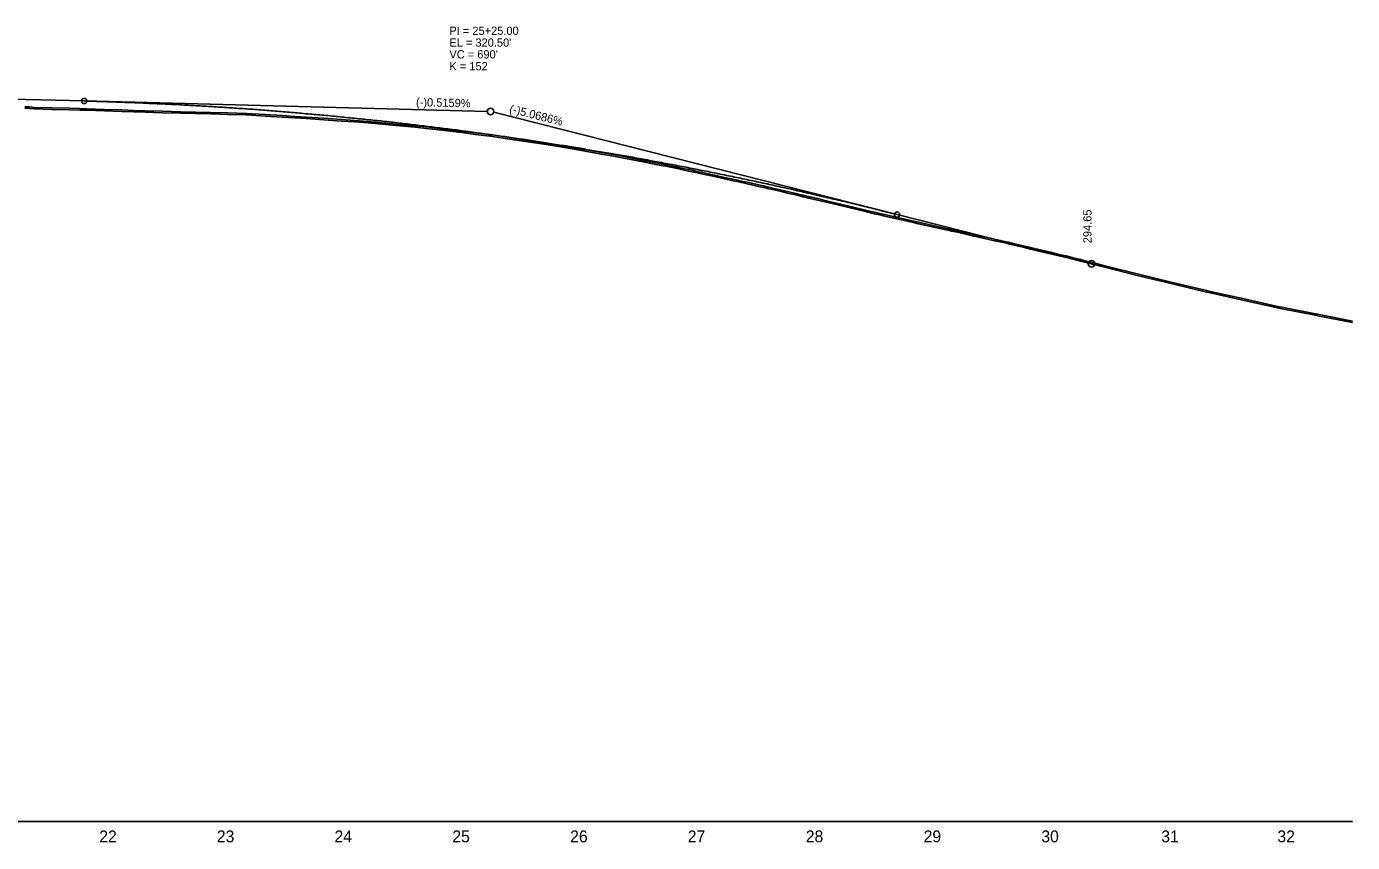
# Model space of a CAD drawing. Extents: x 2111382 to 2119088, y 667477 to 672158.
# Drawn here: x 2113830 to 2114956, y 667477 to 668169 of the extents above; entities that cross this region are included whole.
import ezdxf

# ---------------------------------------------------------------- set-up
doc = ezdxf.new("R2010")
doc.units = 0
for name, color, linetype in [('Exist Profile Cell', 7, 'Continuous'), ('Exist Vertical Profile Ground Line', 7, 'Continuous'), ('Exist Vertical Profile Horizontal Axis Label Major', 7, 'Continuous'), ('Prop Vertical Profile Curve Label', 7, 'Continuous'), ('Prop Vertical Profile Grade', 7, 'Continuous'), ('Prop Vertical Profile Grade Label', 7, 'Continuous'), ('Prop VPI Label', 7, 'Continuous'), ('Scratch_Level_2', 7, 'Continuous')]:
    doc.layers.add(name, color=color, linetype=linetype)

msp = doc.modelspace()

# ---------------------------------------------------------------- linework, layer by layer
at = {"layer": 'Exist Profile Cell'}
msp.add_line((2112699, 667494.5), (2114955.5, 667494.5), dxfattribs=at)
at = {"layer": 'Exist Vertical Profile Ground Line'}
for points in [[(2113828.6, 668099.7), (2113830.4, 668099.7), (2113832.7, 668099.6), (2113836.7, 668099.3), (2113851.5, 668098.8), (2113866.7, 668098.4), (2113875.2, 668098.2), (2113880.9, 668098), (2113896.2, 668097.5), (2113910.9, 668097), (2113921.2, 668096.7), (2113930.8, 668096.3), (2113945.6, 668096), (2113960.8, 668095.6), (2113973.4, 668095.3), (2113986.2, 668095), (2114001, 668094.5), (2114016.3, 668094.2), (2114017.1, 668094.1), (2114032.5, 668093.1), (2114047.1, 668092.3), (2114057.8, 668091.6), (2114067.5, 668091.1), (2114082.3, 668090), (2114097.5, 668088.9), (2114108.4, 668088.2), (2114120, 668087.3), (2114134.8, 668085.9), (2114150, 668084.5), (2114159.9, 668083.6), (2114169.6, 668082.7), (2114184.8, 668080.9), (2114199.6, 668079.1), (2114211.3, 668077.6), (2114223.7, 668076.1), (2114238.4, 668073.9), (2114253.7, 668071.6), (2114267.5, 668069.5), (2114281.9, 668067.3), (2114296.5, 668064.7), (2114311.9, 668062), (2114317.9, 668060.9), (2114325.1, 668059.7), (2114338.5, 668057.2), (2114355, 668054), (2114361.3, 668052.7), (2114368.8, 668051.3), (2114373.8, 668050.3), (2114379.9, 668049.1), (2114381.3, 668048.8), (2114386, 668047.8), (2114392, 668046.5), (2114395.2, 668045.8), (2114398.1, 668045.2), (2114404.2, 668043.9), (2114409.7, 668042.7), (2114410.2, 668042.6), (2114416.3, 668041.2), (2114422.5, 668039.8)], [(2114422.5, 668039.8), (2114428.4, 668038.5), (2114434.5, 668037.2), (2114439.6, 668036.1), (2114440.6, 668035.9), (2114446.6, 668034.6), (2114452.7, 668033.2), (2114455.5, 668032.6), (2114457.3, 668032.1), (2114458.8, 668031.8), (2114464.8, 668030.4), (2114470.9, 668029), (2114476, 668027.8), (2114477, 668027.5), (2114483.1, 668026.2), (2114487.3, 668025.2), (2114489.1, 668024.7), (2114489.9, 668024.6), (2114495.2, 668023.3), (2114501.3, 668021.8), (2114510.3, 668019.7), (2114519.8, 668017.4), (2114542.1, 668012.1), (2114549.8, 668010.3), (2114555.4, 668009), (2114557.3, 668008.6), (2114581.8, 668003.1), (2114587.2, 668001.8), (2114609.3, 667996.9), (2114613.5, 667995.9), (2114615.3, 667995.5), (2114617.1, 667995.1), (2114621.4, 667994.2), (2114627.5, 667992.8), (2114632.9, 667991.6), (2114633.5, 667991.4), (2114634.4, 667991.2), (2114639.6, 667990.1), (2114645.7, 667988.7), (2114651.7, 667987.4), (2114657.8, 667986), (2114662.9, 667984.9), (2114663.9, 667984.6), (2114664.4, 667984.5), (2114669.9, 667983.2), (2114676, 667981.8), (2114682.1, 667980.3), (2114684.6, 667979.7), (2114685.2, 667979.6), (2114686.1, 667979.4), (2114688.1, 667978.9), (2114694.2, 667977.5), (2114700.3, 667976), (2114706.3, 667974.6), (2114712.4, 667973.1), (2114715.2, 667972.5), (2114715.6, 667972.4), (2114718.5, 667971.6), (2114724.6, 667970.1), (2114730.6, 667968.6), (2114736.7, 667967), (2114745.2, 667964.9), (2114775.1, 667957.3), (2114801.5, 667951), (2114831.5, 667943.8), (2114833.5, 667943.3), (2114863.5, 667936.7), (2114893.4, 667930.1), (2114895.6, 667929.7), (2114925.5, 667923.8), (2114925.9, 667923.7), (2114955.5, 667917.9)]]:
    msp.add_lwpolyline(points, dxfattribs=at)
at = {"layer": 'Prop Vertical Profile Curve Label'}
for centre in [(2113879, 668105.9), (2114569, 668009.5)]:
    msp.add_circle(centre, 2.25, dxfattribs=at)
at = {"layer": 'Prop Vertical Profile Grade'}
for p, q in [((2113559, 668114.1), (2113879, 668105.9)), ((2114569, 668009.5), (2114734, 667967.7))]:
    msp.add_line(p, q, dxfattribs=at)
msp.add_spline([(2113879, 668105.9), (2113892.8, 668105.5), (2113906.6, 668105), (2113920.4, 668104.5), (2113934.2, 668103.9), (2113948, 668103.3), (2113961.8, 668102.6), (2113975.6, 668101.8), (2113989.4, 668101), (2114003.2, 668100.1), (2114017, 668099.2), (2114030.8, 668098.2), (2114044.6, 668097.1), (2114058.4, 668095.9), (2114072.2, 668094.7), (2114086, 668093.5), (2114099.8, 668092.1), (2114113.6, 668090.7), (2114127.4, 668089.3), (2114141.2, 668087.8), (2114155, 668086.2), (2114168.8, 668084.5), (2114182.6, 668082.8), (2114196.4, 668081.1), (2114210.2, 668079.2), (2114224, 668077.3), (2114237.8, 668075.4), (2114251.6, 668073.4), (2114265.4, 668071.3), (2114279.2, 668069.1), (2114293, 668066.9), (2114306.8, 668064.6), (2114320.6, 668062.3), (2114334.4, 668059.9), (2114348.2, 668057.5), (2114362, 668054.9), (2114375.8, 668052.3), (2114389.6, 668049.7), (2114403.4, 668047), (2114417.2, 668044.2), (2114431, 668041.4), (2114444.8, 668038.5), (2114458.6, 668035.5), (2114472.4, 668032.5), (2114486.2, 668029.4), (2114500, 668026.2), (2114513.8, 668023), (2114527.6, 668019.8), (2114541.4, 668016.4), (2114555.2, 668013), (2114569, 668009.5)], degree=3, dxfattribs=at)
at = {"layer": 'Prop VPI Label'}
for p, q in [((2113879, 668105.9), (2114221.3, 668097)), ((2114569, 668009.5), (2114226.7, 668096.3))]:
    msp.add_line(p, q, dxfattribs=at)
for centre in [(2114224, 668097), (2114734, 667967.7)]:
    msp.add_circle(centre, 2.75, dxfattribs=at)
at = {"layer": 'Scratch_Level_2'}
for points in [[(2113828.6, 668100.9), (2113830.4, 668100.9), (2113832.7, 668100.9), (2113836.7, 668100.5), (2113851.5, 668100.1), (2113866.7, 668099.7), (2113875.2, 668099.4), (2113880.9, 668099.2), (2113896.2, 668098.7), (2113910.9, 668098.3), (2113921.2, 668097.9), (2113930.8, 668097.6), (2113945.6, 668097.2), (2113960.8, 668096.8), (2113973.4, 668096.5), (2113986.2, 668096.2), (2114001, 668095.8), (2114016.3, 668095.4), (2114017.1, 668095.4), (2114032.5, 668094.4), (2114047.1, 668093.6), (2114057.8, 668092.8), (2114067.5, 668092.3), (2114082.3, 668091.2), (2114097.5, 668090.2), (2114108.4, 668089.4), (2114120, 668088.6), (2114134.8, 668087.2), (2114150, 668085.8), (2114159.9, 668084.9), (2114169.6, 668084), (2114184.8, 668082.1), (2114199.6, 668080.3), (2114211.3, 668078.9), (2114223.7, 668077.4), (2114238.4, 668075.2), (2114253.7, 668072.8), (2114267.5, 668070.7), (2114281.9, 668068.5), (2114296.5, 668065.9), (2114311.9, 668063.3), (2114317.9, 668062.2), (2114325.1, 668061), (2114338.5, 668058.4), (2114355, 668055.2), (2114361.3, 668054), (2114368.8, 668052.6), (2114373.8, 668051.5), (2114379.9, 668050.3), (2114381.3, 668050), (2114386, 668049), (2114392, 668047.8), (2114395.2, 668047.1), (2114398.1, 668046.5), (2114404.2, 668045.1), (2114409.7, 668043.9), (2114410.2, 668043.8), (2114416.3, 668042.5), (2114422.5, 668041.1)], [(2114422.5, 668041.1), (2114428.4, 668039.8), (2114434.5, 668038.5), (2114439.6, 668037.4), (2114440.6, 668037.2), (2114446.6, 668035.8), (2114452.7, 668034.5), (2114455.5, 668033.8), (2114457.3, 668033.4), (2114458.8, 668033), (2114464.8, 668031.6), (2114470.9, 668030.2), (2114476, 668029), (2114477, 668028.8), (2114483.1, 668027.4), (2114487.3, 668026.4), (2114489.1, 668026), (2114489.9, 668025.8), (2114495.2, 668024.5), (2114501.3, 668023.1), (2114510.3, 668020.9), (2114519.8, 668018.7), (2114542.1, 668013.3), (2114549.8, 668011.5), (2114555.4, 668010.2), (2114557.3, 668009.8), (2114581.8, 668004.3), (2114587.2, 668003.1), (2114609.3, 667998.1), (2114613.5, 667997.2), (2114615.3, 667996.8), (2114617.1, 667996.4), (2114621.4, 667995.4), (2114627.5, 667994.1), (2114632.9, 667992.8), (2114633.5, 667992.7), (2114634.4, 667992.5), (2114639.6, 667991.3), (2114645.7, 667990), (2114651.7, 667988.6), (2114657.8, 667987.2), (2114662.9, 667986.1), (2114663.9, 667985.9), (2114664.4, 667985.8), (2114669.9, 667984.5), (2114676, 667983), (2114682.1, 667981.6), (2114684.6, 667981), (2114685.2, 667980.8), (2114686.1, 667980.6), (2114688.1, 667980.1), (2114694.2, 667978.7), (2114700.3, 667977.3), (2114706.3, 667975.8), (2114712.4, 667974.4), (2114715.2, 667973.7), (2114715.6, 667973.6), (2114718.5, 667972.9), (2114724.6, 667971.4), (2114730.6, 667969.8), (2114736.7, 667968.3), (2114745.2, 667966.1), (2114775.1, 667958.6), (2114801.5, 667952.2), (2114831.5, 667945), (2114833.5, 667944.6), (2114863.5, 667938), (2114893.4, 667931.4), (2114895.6, 667930.9), (2114925.5, 667925), (2114925.9, 667925), (2114955.5, 667919.1)]]:
    msp.add_lwpolyline(points, dxfattribs=at)

# ---------------------------------------------------------------- texts
at = {"layer": 'Exist Vertical Profile Horizontal Axis Label Major'}
for s, p in [('22', (2113891.8, 667477)), ('23', (2113991.6, 667477)), ('24', (2114091.5, 667477)), ('25', (2114191.5, 667477)), ('26', (2114291.5, 667477)), ('27', (2114391.3, 667477)), ('28', (2114491.5, 667477)), ('29', (2114591.5, 667477)), ('30', (2114691.4, 667477)), ('31', (2114793.2, 667477)), ('32', (2114891.8, 667477))]:
    msp.add_text(s, height=10, dxfattribs=at).set_placement(p)
at = {"layer": 'Prop Vertical Profile Curve Label'}
for s, p in [("VC = 690'", (2114189, 668142)), ('K = 152', (2114189, 668131.9))]:
    msp.add_text(s, height=7, dxfattribs=at).set_placement(p)
at = {"layer": 'Prop Vertical Profile Grade Label'}
for s, rotation, p in [('(-)0.5159%', 358.5225, (2114160.6, 668101.6)), ('(-)5.0686%', 345.7789, (2114239.4, 668096.2))]:
    msp.add_text(s, height=7, rotation=rotation, dxfattribs=at).set_placement(p)
at = {"layer": 'Prop VPI Label'}
for s, p in [('PI = 25+25.00', (2114189, 668162)), ("EL = 320.50'", (2114189, 668152))]:
    msp.add_text(s, height=7, dxfattribs=at).set_placement(p)
msp.add_text('294.65', height=7, rotation=90, dxfattribs=at).set_placement((2114734, 667985.2))

doc.saveas('drawing.dxf')
